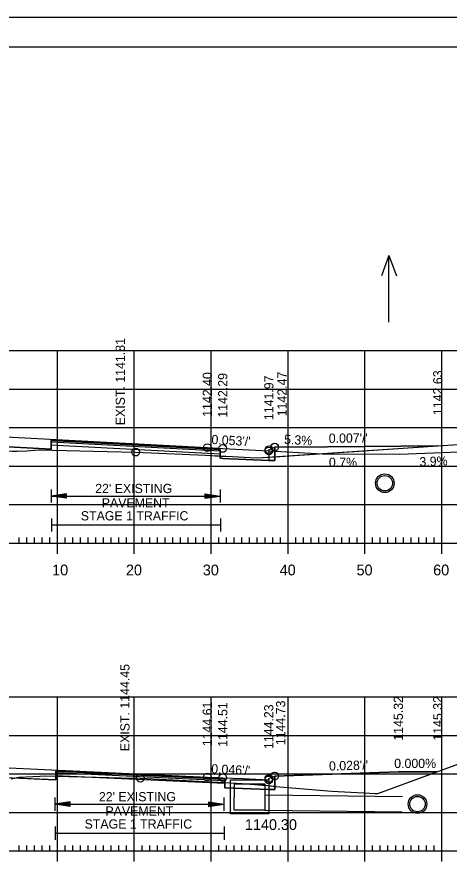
# Model space of a CAD drawing. Extents: x 1322838 to 1324533, y 339903 to 351025.
# Drawn here: x 1323708.5 to 1323764.7, y 342779.4 to 342889.9 of the extents above; entities that cross this region are included whole.
import ezdxf

# ---------------------------------------------------------------- set-up
doc = ezdxf.new("R2010")
doc.units = 0
for name, color, linetype in [('R_Alt Surface', 7, 'Continuous'), ('R_Axis', 7, 'Continuous'), ('R_Axis Annot', 7, 'Continuous'), ('R_Border', 7, 'Continuous'), ('R_Exist Surface', 7, 'Continuous'), ('R_Fin Surface', 7, 'Continuous'), ('R_Fin Surface Annot', 7, 'Continuous'), ('R_Grid', 7, 'Continuous'), ('R_No Plot', 7, 'Continuous'), ('R_Water', 7, 'Continuous'), ('R_Water Annot', 7, 'Continuous'), ('R_Xsect Elev', 7, 'Continuous')]:
    doc.layers.add(name, color=color, linetype=linetype)

msp = doc.modelspace()

# ---------------------------------------------------------------- linework, layer by layer
at = {"layer": 'R_Alt Surface'}
for points in [[(1323658.27, 342835.61), (1323672.22, 342835.89), (1323712.89, 342833.7), (1323712.9, 342834.82), (1323734.89, 342833.64), (1323734.9, 342832.52), (1323735.22, 342832.5), (1323741.22, 342832.21)], [(1323741.22, 342833.47), (1323741.22, 342832.21)], [(1323741.98, 342832.21), (1323741.98, 342833.97)], [(1323741.22, 342832.21), (1323741.98, 342832.21)], [(1323654.69, 342792.29), (1323672.22, 342792.64), (1323713.49, 342790.73), (1323713.5, 342791.85), (1323735.49, 342790.83), (1323735.5, 342789.7), (1323741.21, 342789.48)], [(1323741.21, 342790.73), (1323741.21, 342789.48)], [(1323741.98, 342789.48), (1323741.98, 342791.23)], [(1323741.21, 342789.48), (1323741.98, 342789.48)]]:
    msp.add_lwpolyline(points, dxfattribs=at)
at = {"layer": 'R_Axis'}
for p, q in [((1323708.72, 342821.5), (1323708.72, 342822.2)), ((1323709.72, 342821.5), (1323709.72, 342822.2)), ((1323710.72, 342821.5), (1323710.72, 342822.2)), ((1323711.72, 342821.5), (1323711.72, 342822.2)), ((1323712.72, 342821.5), (1323712.72, 342822.2)), ((1323713.72, 342820.1), (1323713.72, 342822.9)), ((1323714.72, 342821.5), (1323714.72, 342822.2)), ((1323715.72, 342821.5), (1323715.72, 342822.2)), ((1323716.72, 342821.5), (1323716.72, 342822.2)), ((1323717.72, 342821.5), (1323717.72, 342822.2)), ((1323718.72, 342821.5), (1323718.72, 342822.2)), ((1323719.72, 342821.5), (1323719.72, 342822.2)), ((1323720.72, 342821.5), (1323720.72, 342822.2)), ((1323721.72, 342821.5), (1323721.72, 342822.2)), ((1323722.72, 342821.5), (1323722.72, 342822.2)), ((1323723.72, 342820.1), (1323723.72, 342822.9)), ((1323724.72, 342821.5), (1323724.72, 342822.2)), ((1323725.72, 342821.5), (1323725.72, 342822.2)), ((1323726.72, 342821.5), (1323726.72, 342822.2)), ((1323727.72, 342821.5), (1323727.72, 342822.2)), ((1323728.72, 342821.5), (1323728.72, 342822.2)), ((1323729.72, 342821.5), (1323729.72, 342822.2)), ((1323730.72, 342821.5), (1323730.72, 342822.2)), ((1323731.72, 342821.5), (1323731.72, 342822.2)), ((1323732.72, 342821.5), (1323732.72, 342822.2)), ((1323733.72, 342820.1), (1323733.72, 342822.9)), ((1323734.72, 342821.5), (1323734.72, 342822.2)), ((1323735.72, 342821.5), (1323735.72, 342822.2)), ((1323736.72, 342821.5), (1323736.72, 342822.2)), ((1323737.72, 342821.5), (1323737.72, 342822.2)), ((1323738.72, 342821.5), (1323738.72, 342822.2)), ((1323739.72, 342821.5), (1323739.72, 342822.2)), ((1323740.72, 342821.5), (1323740.72, 342822.2)), ((1323741.72, 342821.5), (1323741.72, 342822.2)), ((1323742.72, 342821.5), (1323742.72, 342822.2)), ((1323743.72, 342820.1), (1323743.72, 342822.9)), ((1323744.72, 342821.5), (1323744.72, 342822.2)), ((1323745.72, 342821.5), (1323745.72, 342822.2)), ((1323746.72, 342821.5), (1323746.72, 342822.2)), ((1323747.72, 342821.5), (1323747.72, 342822.2)), ((1323748.72, 342821.5), (1323748.72, 342822.2)), ((1323749.72, 342821.5), (1323749.72, 342822.2)), ((1323750.72, 342821.5), (1323750.72, 342822.2)), ((1323751.72, 342821.5), (1323751.72, 342822.2)), ((1323752.72, 342821.5), (1323752.72, 342822.2)), ((1323753.72, 342820.1), (1323753.72, 342822.9)), ((1323754.72, 342821.5), (1323754.72, 342822.2)), ((1323755.72, 342821.5), (1323755.72, 342822.2)), ((1323756.72, 342821.5), (1323756.72, 342822.2)), ((1323757.72, 342821.5), (1323757.72, 342822.2)), ((1323758.72, 342821.5), (1323758.72, 342822.2)), ((1323759.72, 342821.5), (1323759.72, 342822.2)), ((1323760.72, 342821.5), (1323760.72, 342822.2)), ((1323761.72, 342821.5), (1323761.72, 342822.2)), ((1323762.72, 342821.5), (1323762.72, 342822.2)), ((1323763.72, 342820.1), (1323763.72, 342822.9)), ((1323563.72, 342821.5), (1323843.72, 342821.5)), ((1323713.72, 342780.1), (1323713.72, 342782.9)), ((1323723.72, 342780.1), (1323723.72, 342782.9)), ((1323733.72, 342780.1), (1323733.72, 342782.9)), ((1323743.72, 342780.1), (1323743.72, 342782.9)), ((1323753.72, 342780.1), (1323753.72, 342782.9)), ((1323763.72, 342780.1), (1323763.72, 342782.9)), ((1323563.72, 342781.5), (1323843.72, 342781.5)), ((1323708.72, 342781.5), (1323708.72, 342782.2)), ((1323709.72, 342781.5), (1323709.72, 342782.2)), ((1323710.72, 342781.5), (1323710.72, 342782.2)), ((1323711.72, 342781.5), (1323711.72, 342782.2)), ((1323712.72, 342781.5), (1323712.72, 342782.2)), ((1323714.72, 342781.5), (1323714.72, 342782.2)), ((1323715.72, 342781.5), (1323715.72, 342782.2)), ((1323716.72, 342781.5), (1323716.72, 342782.2)), ((1323717.72, 342781.5), (1323717.72, 342782.2)), ((1323718.72, 342781.5), (1323718.72, 342782.2)), ((1323719.72, 342781.5), (1323719.72, 342782.2)), ((1323720.72, 342781.5), (1323720.72, 342782.2)), ((1323721.72, 342781.5), (1323721.72, 342782.2)), ((1323722.72, 342781.5), (1323722.72, 342782.2)), ((1323724.72, 342781.5), (1323724.72, 342782.2)), ((1323725.72, 342781.5), (1323725.72, 342782.2)), ((1323726.72, 342781.5), (1323726.72, 342782.2)), ((1323727.72, 342781.5), (1323727.72, 342782.2)), ((1323728.72, 342781.5), (1323728.72, 342782.2)), ((1323729.72, 342781.5), (1323729.72, 342782.2)), ((1323730.72, 342781.5), (1323730.72, 342782.2)), ((1323731.72, 342781.5), (1323731.72, 342782.2)), ((1323732.72, 342781.5), (1323732.72, 342782.2)), ((1323734.72, 342781.5), (1323734.72, 342782.2)), ((1323735.72, 342781.5), (1323735.72, 342782.2)), ((1323736.72, 342781.5), (1323736.72, 342782.2)), ((1323737.72, 342781.5), (1323737.72, 342782.2)), ((1323738.72, 342781.5), (1323738.72, 342782.2)), ((1323739.72, 342781.5), (1323739.72, 342782.2)), ((1323740.72, 342781.5), (1323740.72, 342782.2)), ((1323741.72, 342781.5), (1323741.72, 342782.2)), ((1323742.72, 342781.5), (1323742.72, 342782.2)), ((1323744.72, 342781.5), (1323744.72, 342782.2)), ((1323745.72, 342781.5), (1323745.72, 342782.2)), ((1323746.72, 342781.5), (1323746.72, 342782.2)), ((1323747.72, 342781.5), (1323747.72, 342782.2)), ((1323748.72, 342781.5), (1323748.72, 342782.2)), ((1323749.72, 342781.5), (1323749.72, 342782.2)), ((1323750.72, 342781.5), (1323750.72, 342782.2)), ((1323751.72, 342781.5), (1323751.72, 342782.2)), ((1323752.72, 342781.5), (1323752.72, 342782.2)), ((1323754.72, 342781.5), (1323754.72, 342782.2)), ((1323755.72, 342781.5), (1323755.72, 342782.2)), ((1323756.72, 342781.5), (1323756.72, 342782.2)), ((1323757.72, 342781.5), (1323757.72, 342782.2)), ((1323758.72, 342781.5), (1323758.72, 342782.2)), ((1323759.72, 342781.5), (1323759.72, 342782.2)), ((1323760.72, 342781.5), (1323760.72, 342782.2)), ((1323761.72, 342781.5), (1323761.72, 342782.2)), ((1323762.72, 342781.5), (1323762.72, 342782.2))]:
    msp.add_line(p, q, dxfattribs=at)
at = {"layer": 'R_Axis Annot'}
for p, q in [((1323712.89, 342828.46), (1323712.89, 342826.76)), ((1323714.89, 342827.91), (1323712.89, 342827.61)), ((1323714.89, 342827.86), (1323713.23, 342827.61)), ((1323714.89, 342827.81), (1323713.57, 342827.61)), ((1323714.89, 342827.76), (1323713.9, 342827.61)), ((1323714.89, 342827.31), (1323714.89, 342827.91)), ((1323732.89, 342827.91), (1323734.89, 342827.61)), ((1323732.89, 342827.91), (1323732.89, 342827.31)), ((1323732.89, 342827.86), (1323734.56, 342827.61)), ((1323732.89, 342827.81), (1323734.21, 342827.61)), ((1323732.89, 342827.76), (1323733.88, 342827.61)), ((1323734.89, 342828.46), (1323734.89, 342826.76)), ((1323714.89, 342827.31), (1323712.89, 342827.61)), ((1323712.89, 342827.61), (1323734.89, 342827.61)), ((1323714.89, 342827.36), (1323713.23, 342827.61)), ((1323714.89, 342827.41), (1323713.57, 342827.61)), ((1323714.89, 342827.46), (1323713.9, 342827.61)), ((1323714.89, 342827.71), (1323714.24, 342827.61)), ((1323714.89, 342827.51), (1323714.24, 342827.61)), ((1323714.89, 342827.66), (1323714.58, 342827.61)), ((1323714.89, 342827.56), (1323714.58, 342827.61)), ((1323732.89, 342827.71), (1323733.54, 342827.61)), ((1323732.89, 342827.66), (1323733.21, 342827.61)), ((1323732.89, 342827.31), (1323734.89, 342827.61)), ((1323732.89, 342827.51), (1323733.54, 342827.61)), ((1323732.89, 342827.41), (1323734.21, 342827.61)), ((1323732.89, 342827.36), (1323734.56, 342827.61)), ((1323732.89, 342827.46), (1323733.88, 342827.61)), ((1323732.89, 342827.56), (1323733.21, 342827.61)), ((1323712.93, 342824.7), (1323712.93, 342822.99)), ((1323734.93, 342824.7), (1323734.93, 342822.99)), ((1323712.93, 342823.85), (1323734.93, 342823.85)), ((1323713.38, 342788.42), (1323713.38, 342786.72)), ((1323735.38, 342788.42), (1323735.38, 342786.72)), ((1323715.38, 342787.87), (1323713.38, 342787.57)), ((1323715.38, 342787.27), (1323713.38, 342787.57)), ((1323713.38, 342787.57), (1323735.38, 342787.57)), ((1323715.38, 342787.82), (1323713.71, 342787.57)), ((1323715.38, 342787.32), (1323713.71, 342787.57)), ((1323715.38, 342787.77), (1323714.06, 342787.57)), ((1323715.38, 342787.37), (1323714.06, 342787.57)), ((1323715.38, 342787.72), (1323714.39, 342787.57)), ((1323715.38, 342787.42), (1323714.39, 342787.57)), ((1323715.38, 342787.67), (1323714.73, 342787.57)), ((1323715.38, 342787.47), (1323714.73, 342787.57)), ((1323715.38, 342787.62), (1323715.06, 342787.57)), ((1323715.38, 342787.52), (1323715.06, 342787.57)), ((1323715.38, 342787.27), (1323715.38, 342787.87)), ((1323733.38, 342787.87), (1323735.38, 342787.57)), ((1323733.38, 342787.87), (1323733.38, 342787.27)), ((1323733.38, 342787.82), (1323735.04, 342787.57)), ((1323733.38, 342787.77), (1323734.7, 342787.57)), ((1323733.38, 342787.72), (1323734.37, 342787.57)), ((1323733.38, 342787.67), (1323734.03, 342787.57)), ((1323733.38, 342787.62), (1323733.69, 342787.57)), ((1323733.38, 342787.27), (1323735.38, 342787.57)), ((1323733.38, 342787.47), (1323734.03, 342787.57)), ((1323733.38, 342787.37), (1323734.7, 342787.57)), ((1323733.38, 342787.32), (1323735.04, 342787.57)), ((1323733.38, 342787.42), (1323734.37, 342787.57)), ((1323733.38, 342787.52), (1323733.69, 342787.57)), ((1323713.41, 342784.66), (1323713.41, 342782.95)), ((1323735.41, 342784.66), (1323735.41, 342782.95)), ((1323713.41, 342783.8), (1323735.41, 342783.8))]:
    msp.add_line(p, q, dxfattribs=at)
at = {"layer": 'R_Border'}
msp.add_line((1323545.72, 342885.96), (1323861.9, 342885.96), dxfattribs=at)
at = {"layer": 'R_Exist Surface'}
for points in [[(1323633.35, 342833.15), (1323667.32, 342835.2), (1323668.78, 342835.23), (1323681.59, 342834.51), (1323684.8, 342834.79), (1323688.99, 342834.48), (1323692.04, 342833.66), (1323697.78, 342833.66), (1323700.44, 342833.57), (1323701.8, 342833.55), (1323707.81, 342833.43), (1323708.46, 342833.43), (1323709.72, 342833.5), (1323711.29, 342833.59), (1323720.19, 342833.39), (1323723.89, 342833.31), (1323732.96, 342832.9), (1323736.51, 342832.73), (1323738.8, 342832.61), (1323739.73, 342832.57), (1323770.35, 342834.6)], [(1323707.68, 342790.88), (1323708.71, 342791.06), (1323711.41, 342791.2), (1323712.2, 342791.24), (1323722.02, 342791), (1323724.49, 342790.95), (1323736.28, 342790.33), (1323737.73, 342790.26), (1323740.38, 342790.04), (1323740.59, 342790.02), (1323742.13, 342789.88), (1323749.42, 342789.25), (1323754.34, 342789.02), (1323755.06, 342788.94), (1323755.39, 342788.96), (1323766.76, 342793.12)]]:
    msp.add_lwpolyline(points, dxfattribs=at)
for centre in [(1323756.31, 342829.27), (1323760.56, 342787.58)]:
    msp.add_circle(centre, 1.21, dxfattribs=at)
at = {"layer": 'R_Fin Surface'}
for points in [[(1323640.29, 342833.57), (1323644.22, 342832.26), (1323644.22, 342832.26), (1323658.27, 342835.61), (1323663.58, 342836.87), (1323666.22, 342837.5), (1323672.22, 342837.18), (1323674.22, 342837.07), (1323674.22, 342837.07), (1323703.47, 342835.5), (1323703.72, 342835.48), (1323733.21, 342833.9), (1323733.22, 342833.9), (1323735.22, 342833.79), (1323741.22, 342833.47), (1323741.22, 342833.52), (1323741.23, 342833.63), (1323741.98, 342833.97), (1323748.84, 342834.02), (1323763.2, 342834.13)], [(1323648.3, 342791.23), (1323654.69, 342792.29), (1323666.22, 342794.21), (1323666.56, 342794.2), (1323672.22, 342793.93), (1323673.38, 342793.88), (1323674.22, 342793.84), (1323674.22, 342793.84), (1323695.24, 342792.86), (1323703.71, 342792.47), (1323703.72, 342792.47), (1323733.21, 342791.1), (1323733.21, 342791.1), (1323734.69, 342791.03), (1323735.22, 342791.01), (1323737.86, 342790.89), (1323741.21, 342790.73), (1323741.22, 342790.9), (1323741.61, 342791.07), (1323741.98, 342791.23), (1323741.98, 342791.23), (1323758.06, 342791.77), (1323763.06, 342791.77)]]:
    msp.add_lwpolyline(points, dxfattribs=at)
at = {"layer": 'R_Grid'}
for p, q in [((1323563.72, 342846.5), (1323843.72, 342846.5)), ((1323713.72, 342821.5), (1323713.72, 342846.5)), ((1323723.72, 342821.5), (1323723.72, 342846.5)), ((1323733.72, 342821.5), (1323733.72, 342846.5)), ((1323743.72, 342821.5), (1323743.72, 342846.5)), ((1323753.72, 342821.5), (1323753.72, 342846.5)), ((1323763.72, 342821.5), (1323763.72, 342846.5)), ((1323563.72, 342841.5), (1323843.72, 342841.5)), ((1323563.72, 342836.5), (1323843.72, 342836.5)), ((1323563.72, 342831.5), (1323843.72, 342831.5)), ((1323563.72, 342826.5), (1323843.72, 342826.5)), ((1323563.72, 342821.5), (1323843.72, 342821.5)), ((1323563.72, 342801.5), (1323843.72, 342801.5)), ((1323713.72, 342781.5), (1323713.72, 342801.5)), ((1323723.72, 342781.5), (1323723.72, 342801.5)), ((1323733.72, 342781.5), (1323733.72, 342801.5)), ((1323743.72, 342781.5), (1323743.72, 342801.5)), ((1323753.72, 342781.5), (1323753.72, 342801.5)), ((1323763.72, 342781.5), (1323763.72, 342801.5)), ((1323563.72, 342796.5), (1323843.72, 342796.5)), ((1323563.72, 342791.5), (1323843.72, 342791.5)), ((1323563.72, 342786.5), (1323843.72, 342786.5)), ((1323563.72, 342781.5), (1323843.72, 342781.5))]:
    msp.add_line(p, q, dxfattribs=at)
at = {"layer": 'R_No Plot'}
for p, q in [((1323533.31, 342889.85), (1323866.65, 342889.85)), ((1323712.87, 342834.28), (1323734.87, 342833.1)), ((1323713.48, 342791.31), (1323735.47, 342790.29))]:
    msp.add_line(p, q, dxfattribs=at)
for points in [[(1323533.31, 342889.85), (1323866.65, 342889.85), (1323866.65, 342676.51), (1323533.31, 342676.51)], [(1323779.64, 342885.96), (1323799.26, 342885.96), (1323799.26, 342876.08), (1323815.37, 342876.08), (1323838.57, 342876.08), (1323838.57, 342843.41), (1323861.77, 342843.41), (1323861.9, 342680.5), (1323545.72, 342680.5), (1323545.72, 342885.96)], [(1323652.91, 342834.33), (1323667.32, 342835.2), (1323668.78, 342835.23), (1323681.59, 342834.51), (1323684.8, 342834.79), (1323688.99, 342834.48), (1323692.04, 342833.66), (1323697.78, 342833.66), (1323700.44, 342833.57), (1323701.8, 342833.55), (1323707.81, 342833.43), (1323708.46, 342833.43), (1323709.72, 342833.5), (1323711.29, 342833.59), (1323720.19, 342833.39), (1323723.89, 342833.31), (1323732.96, 342832.9), (1323734.9, 342832.8), (1323734.89, 342833.64), (1323712.9, 342834.82), (1323712.89, 342833.7), (1323672.22, 342835.89), (1323658.27, 342835.61)], [(1323741.98, 342832.72), (1323763.2, 342834.13), (1323748.84, 342834.02), (1323741.98, 342833.97)], [(1323734.9, 342832.8), (1323736.51, 342832.73), (1323738.8, 342832.61), (1323739.73, 342832.57), (1323741.98, 342832.72), (1323741.98, 342832.21), (1323741.22, 342832.21), (1323735.22, 342832.5), (1323734.9, 342832.52)], [(1323713.49, 342791.21), (1323722.02, 342791), (1323724.49, 342790.95), (1323735.49, 342790.37), (1323735.49, 342790.83), (1323713.5, 342791.85)], [(1323741.98, 342789.89), (1323742.13, 342789.88), (1323749.42, 342789.25), (1323754.34, 342789.02), (1323755.06, 342788.94), (1323755.39, 342788.96), (1323763.06, 342791.77), (1323758.06, 342791.77), (1323741.98, 342791.23), (1323741.98, 342791.23)], [(1323708.19, 342790.97), (1323708.71, 342791.06), (1323711.41, 342791.2), (1323712.2, 342791.24), (1323713.49, 342791.21), (1323713.49, 342790.73)], [(1323735.49, 342790.37), (1323736.28, 342790.33), (1323737.73, 342790.26), (1323740.38, 342790.04), (1323740.59, 342790.02), (1323741.98, 342789.89), (1323741.98, 342789.48), (1323741.21, 342789.48), (1323735.5, 342789.7)]]:
    msp.add_lwpolyline(points, close=True, dxfattribs=at)
for points in [[(1323712.9, 342834.66), (1323734.89, 342833.47)], [(1323741.22, 342833.47), (1323748.21, 342833.1), (1323758.21, 342833.03), (1323768.2, 342833.42), (1323778.85, 342834.44)], [(1323713.5, 342791.68), (1323735.49, 342790.66)]]:
    msp.add_lwpolyline(points, dxfattribs=at)
for centre in [(1323733.22, 342833.9), (1323733.22, 342833.9), (1323741.98, 342833.97), (1323741.98, 342833.97), (1323741.98, 342833.97), (1323723.89, 342833.31), (1323735.22, 342833.79), (1323735.22, 342833.79), (1323741.22, 342833.47), (1323741.22, 342833.47), (1323741.23, 342833.63), (1323724.49, 342790.95), (1323733.21, 342791.1), (1323733.21, 342791.1), (1323735.22, 342791.01), (1323735.22, 342791.01), (1323741.22, 342790.9), (1323741.22, 342790.9), (1323741.98, 342791.23), (1323741.98, 342791.23), (1323741.98, 342791.23), (1323741.21, 342790.73), (1323741.21, 342790.73)]:
    msp.add_circle(centre, 0.5, dxfattribs=at)
at = {"layer": 'R_Water'}
for p, q in [((1323740.74, 342788.8), (1323758.59, 342788.58)), ((1323740.71, 342786.8), (1323758.56, 342786.58))]:
    msp.add_line(p, q, dxfattribs=at)
for points in [[(1323738.71, 342790.73), (1323741.21, 342790.73), (1323741.21, 342786.3), (1323738.71, 342786.3), (1323736.21, 342786.3), (1323736.21, 342790.73)], [(1323738.75, 342790.23), (1323740.71, 342790.23), (1323740.71, 342786.8), (1323738.71, 342786.8), (1323736.71, 342786.8), (1323736.77, 342790.23)]]:
    msp.add_lwpolyline(points, close=True, dxfattribs=at)
for centre in [(1323756.31, 342829.27), (1323760.56, 342787.58)]:
    msp.add_circle(centre, 1, dxfattribs=at)
at = {"layer": 'R_Water Annot'}
for p, q in [((1323756.84, 342858.87), (1323755.87, 342856.21)), ((1323756.84, 342850.18), (1323756.84, 342858.87)), ((1323756.84, 342858.87), (1323757.81, 342856.21))]:
    msp.add_line(p, q, dxfattribs=at)

# ---------------------------------------------------------------- texts
at = {"layer": 'R_Axis Annot'}
for s, height, p in [("22' EXISTING ", 1.2, (1323718.63, 342827.99)), ('PAVEMENT', 1.2, (1323719.48, 342826.12)), ('STAGE 1 TRAFFIC', 1.2, (1323716.76, 342824.44)), ('10', 1.4, (1323713.03, 342817.3)), ('20', 1.4, (1323722.63, 342817.3)), ('30', 1.4, (1323732.63, 342817.3)), ('40', 1.4, (1323742.63, 342817.3)), ('50', 1.4, (1323752.63, 342817.3)), ('60', 1.4, (1323762.6, 342817.3)), ("22' EXISTING ", 1.2, (1323719.11, 342787.94)), ('PAVEMENT', 1.2, (1323719.96, 342786.08)), ('STAGE 1 TRAFFIC', 1.2, (1323717.25, 342784.4)), ('1140.30', 1.4, (1323738.11, 342784.22))]:
    msp.add_text(s, height=height, dxfattribs=at).set_placement(p)
at = {"layer": 'R_Fin Surface Annot'}
for s, rotation, p in [('1142.40', 90, (1323733.82, 342837.9)), ('1142.29', 90, (1323735.82, 342837.79)), ('1141.97', 90, (1323741.82, 342837.47)), ('1142.47', 90, (1323743.53, 342837.97)), ('1142.63', 90, (1323763.8, 342838.13)), ("0.053'/'", 356.9235, (1323733.73, 342834.37)), ("0.007'/'", 0.4292, (1323749.02, 342834.52)), ('1145.32', 90, (1323758.66, 342795.82)), ('1145.32', 90, (1323763.8, 342795.82)), ('1144.61', 90, (1323733.81, 342795.1)), ('1144.51', 90, (1323735.82, 342795.01)), ('1144.23', 90, (1323741.81, 342794.73)), ('1144.73', 90, (1323743.35, 342795.23)), ("0.046'/'", 357.3448, (1323733.7, 342791.58)), ("0.028'/'", 1.5843, (1323749.06, 342791.93))]:
    msp.add_text(s, height=1.2, rotation=rotation, dxfattribs=at).set_placement(p)
msp.add_text('0.000%', height=1.2, dxfattribs=at).set_placement((1323757.53, 342792.27))
at = {"layer": 'R_No Plot'}
for s, rotation, p in [('5.3%', 356.967, (1323743.18, 342834.39)), ('0.7%', 359.607, (1323749.03, 342831.4)), ('3.9%', 2.247, (1323760.84, 342831.45))]:
    msp.add_text(s, height=1.2, rotation=rotation, dxfattribs=at).set_placement(p)
at = {"layer": 'R_Xsect Elev'}
for s, p in [('EXIST. 1141.81', (1323722.49, 342836.81)), ('EXIST. 1144.45', (1323723.09, 342794.45))]:
    msp.add_text(s, height=1.2, rotation=90, dxfattribs=at).set_placement(p)

doc.saveas('drawing.dxf')
